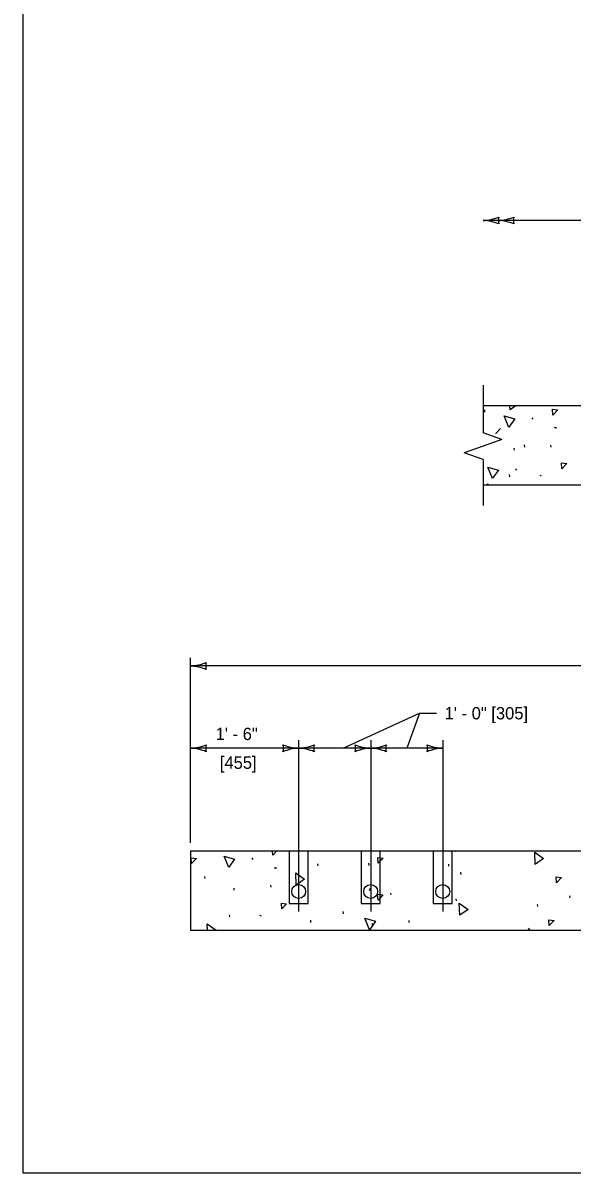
# Model space of a CAD drawing. Extents: x 49991.4 to 50021, y 49987.6 to 50011.4.
# Drawn here: x 49999.38 to 50002.06, y 49987.8 to 49993.39 of the extents above; entities that cross this region are included whole.
import ezdxf

# ---------------------------------------------------------------- set-up
doc = ezdxf.new("R2010")
doc.units = 0
for name, color, linetype in [('Level 1', 7, 'Continuous'), ('Level 2', 7, 'Continuous'), ('Level 3', 7, 'Continuous'), ('Level 4', 7, 'Continuous'), ('Level 5', 7, 'Continuous'), ('Level 6', 7, 'Continuous'), ('Level 9', 7, 'Continuous')]:
    doc.layers.add(name, color=color, linetype=linetype)

msp = doc.modelspace()

# ---------------------------------------------------------------- linework, layer by layer
at = {"layer": 'Level 1'}
for p, q in [((50001.6187, 49991.5298), (50007.3102, 49991.5298)), ((50001.6187, 49991.1448), (50003.1125, 49991.1448)), ((50008.5975, 49989.3638), (50000.1975, 49989.3638)), ((50000.1975, 49989.3638), (50000.1975, 49988.9788)), ((50000.1975, 49988.9788), (50008.5975, 49988.9788))]:
    msp.add_line(p, q, dxfattribs=at)
msp.add_lwpolyline([(49999.3835, 49998.9992), (50016.7501, 49998.9992), (50016.7501, 49987.7988), (49999.3835, 49987.7988)], close=True, dxfattribs=at)
at = {"layer": 'Level 3'}
for p, q in [((50003.1103, 49992.4298), (50001.6187, 49992.4298)), ((50000.1973, 49989.4039), (50000.1973, 49990.3039)), ((50004.3975, 49990.2638), (50000.1975, 49990.2638)), ((50001.31, 49990.0342), (50001.392, 49990.0342)), ((50000.7225, 49989.8638), (50000.1975, 49989.8638)), ((50001.0725, 49989.8638), (50000.7225, 49989.8638)), ((50001.4225, 49989.8638), (50001.0725, 49989.8638)), ((50001.0663, 49989.1728), (50001.0721, 49989.1859))]:
    msp.add_line(p, q, dxfattribs=at)
msp.add_lwpolyline([(50000.9387, 49989.8638), (50001.31, 49990.0342), (50001.2475, 49989.8638)], dxfattribs=at)
for centre in [(50000.7225, 49989.1676), (50001.0725, 49989.1676), (50001.4225, 49989.1676)]:
    msp.add_circle(centre, 0.0338, dxfattribs=at)
for centre, radius, start, end in [((50001.6096, 49992.6519), 0.2223, 272.3605, 292.544), ((50001.6072, 49992.1971), 0.233, 67.9228, 87.1727), ((50001.7469, 49992.4298), 0.0548, 162.1388, 197.8612), ((50001.683, 49992.6519), 0.2223, 272.3605, 292.544), ((50001.6807, 49992.1971), 0.233, 67.9228, 87.1727), ((50001.8204, 49992.4298), 0.0548, 162.1388, 197.8612), ((50000.1883, 49990.486), 0.2223, 272.3605, 292.544), ((50000.186, 49990.0311), 0.233, 67.9228, 87.1727), ((50000.3257, 49990.2638), 0.0548, 162.1388, 197.8612), ((50000.1883, 49990.086), 0.2223, 272.3605, 292.544), ((50000.186, 49989.6311), 0.233, 67.9228, 87.1727), ((50000.3257, 49989.8638), 0.0548, 162.1388, 197.8612), ((50000.5943, 49989.8638), 0.0548, 342.1388, 17.8612), ((50000.734, 49990.0966), 0.233, 247.9228, 267.1727), ((50000.7317, 49989.6417), 0.2223, 92.3605, 112.544), ((50000.7133, 49990.086), 0.2223, 272.3605, 292.544), ((50000.711, 49989.6311), 0.233, 67.9228, 87.1727), ((50000.8507, 49989.8638), 0.0548, 162.1388, 197.8612), ((50000.9443, 49989.8638), 0.0548, 342.1388, 17.8612), ((50001.084, 49990.0966), 0.233, 247.9228, 267.1727), ((50001.0817, 49989.6417), 0.2223, 92.3605, 112.544), ((50001.0633, 49990.086), 0.2223, 272.3605, 292.544), ((50001.061, 49989.6311), 0.233, 67.9228, 87.1727), ((50001.2007, 49989.8638), 0.0548, 162.1388, 197.8612), ((50001.2943, 49989.8638), 0.0548, 342.1388, 17.8612), ((50001.434, 49990.0966), 0.233, 247.9228, 267.1727), ((50001.4317, 49989.6417), 0.2223, 92.3605, 112.544)]:
    msp.add_arc(centre, radius, start, end, dxfattribs=at)
at = {"layer": 'Level 4'}
for p, q in [((50001.6276, 49991.4986), (50001.6265, 49991.5087)), ((50001.8556, 49991.4708), (50001.8611, 49991.4633)), ((50001.9639, 49991.4247), (50001.9706, 49991.4213)), ((50001.9687, 49991.4247), (50001.9754, 49991.4214)), ((50001.771, 49991.3133), (50001.7699, 49991.3234)), ((50001.8216, 49991.3283), (50001.8206, 49991.3384)), ((50001.9493, 49991.3276), (50001.9483, 49991.3377)), ((50001.7486, 49991.1842), (50001.7475, 49991.1943)), ((50001.7758, 49991.2227), (50001.7814, 49991.2152)), ((50001.8939, 49991.1915), (50001.9006, 49991.1882)), ((50000.4947, 49989.3309), (50000.5002, 49989.3234)), ((50000.8175, 49989.2924), (50000.8164, 49989.3026)), ((50001.0649, 49989.2944), (50001.0638, 49989.3045)), ((50001.453, 49989.2908), (50001.4519, 49989.301)), ((50000.2684, 49989.2303), (50000.2673, 49989.2405)), ((50000.603, 49989.2848), (50000.6097, 49989.2815)), ((50000.6078, 49989.2848), (50000.6145, 49989.2815)), ((50001.5116, 49989.2505), (50001.5106, 49989.2607)), ((50000.4101, 49989.1734), (50000.409, 49989.1835)), ((50000.5885, 49989.1877), (50000.5874, 49989.1978)), ((50001.1664, 49989.16), (50001.172, 49989.1524)), ((50001.4893, 49989.1214), (50001.4882, 49989.1316)), ((50002.0417, 49989.1365), (50002.0406, 49989.1466)), ((50000.9401, 49989.0593), (50000.939, 49989.0695)), ((50001.884, 49989.0946), (50001.883, 49989.1047)), ((50000.3877, 49989.0443), (50000.3867, 49989.0544)), ((50000.533, 49989.0516), (50000.5397, 49989.0483)), ((50000.7825, 49989.0174), (50000.7814, 49989.0275)), ((50001.0818, 49989.0024), (50001.0808, 49989.0126)), ((50001.2602, 49989.0167), (50001.2591, 49989.0269)), ((50001.8382, 49988.989), (50001.8438, 49988.9814))]:
    msp.add_line(p, q, dxfattribs=at)
for points in [[(50001.7495, 49991.5091), (50001.7488, 49991.5298)], [(50001.7793, 49991.5298), (50001.7504, 49991.5097)], [(50001.7438, 49991.424), (50001.7213, 49991.4793), (50001.7726, 49991.4647), (50001.7444, 49991.4248)], [(50001.9576, 49991.4832), (50001.9554, 49991.5119), (50001.9811, 49991.5088), (50001.9576, 49991.4832)], [(50001.7033, 49991.4191), (50001.7034, 49991.4191), (50001.6798, 49991.3936)], [(50001.6798, 49991.3936), (50001.6797, 49991.3955)], [(50002.0016, 49991.2226), (50001.9994, 49991.2512), (50002.0251, 49991.2481), (50002.0016, 49991.2226)], [(50001.664, 49991.1758), (50001.6415, 49991.2312), (50001.6928, 49991.2166), (50001.6646, 49991.1766)], [(50001.6395, 49991.1448), (50001.6393, 49991.1498), (50001.6462, 49991.1448)], [(50000.5967, 49989.3433), (50000.5951, 49989.3638)], [(50000.6156, 49989.3638), (50000.5967, 49989.3433)], [(50001.4844, 49989.3612), (50001.4833, 49989.3638)], [(50001.4864, 49989.3638), (50001.4851, 49989.362)], [(50001.8716, 49989.2993), (50001.8694, 49989.3591), (50001.9126, 49989.3278), (50001.8725, 49989.2998)], [(50000.2027, 49989.3031), (50000.2005, 49989.3317), (50000.2262, 49989.3286), (50000.2027, 49989.3031)], [(50000.3829, 49989.2841), (50000.3604, 49989.3394), (50000.4117, 49989.3248), (50000.3835, 49989.2849)], [(50001.1089, 49989.3044), (50001.1067, 49989.3331), (50001.1324, 49989.33), (50001.1089, 49989.3044)], [(50000.7104, 49989.1983), (50000.7082, 49989.258), (50000.7514, 49989.2267), (50000.7113, 49989.1988)], [(50001.976, 49989.2093), (50001.9738, 49989.2379), (50001.9995, 49989.2348), (50001.976, 49989.2093)], [(50001.1086, 49989.1257), (50001.1064, 49989.1544), (50001.1321, 49989.1513), (50001.1086, 49989.1257)], [(50000.6407, 49989.0827), (50000.6385, 49989.1113), (50000.6642, 49989.1082), (50000.6407, 49989.0827)], [(50001.5052, 49989.0516), (50001.503, 49989.1113), (50001.5462, 49989.08), (50001.5061, 49989.0521)], [(50000.2795, 49988.9788), (50000.2784, 49989.0099), (50000.3212, 49988.9788)], [(50001.0671, 49988.9816), (50001.0446, 49989.037), (50001.0959, 49989.0224), (50001.0678, 49988.9824)], [(50001.9402, 49989.0014), (50001.938, 49989.03), (50001.9638, 49989.0269), (50001.9402, 49989.0014)]]:
    msp.add_lwpolyline(points, dxfattribs=at)
at = {"layer": 'Level 5'}
for p, q in [((50000.7225, 49989.9038), (50000.7225, 49989.0708)), ((50001.0725, 49989.9038), (50001.0725, 49989.0708)), ((50001.4225, 49989.9038), (50001.4225, 49989.0708))]:
    msp.add_line(p, q, dxfattribs=at)
at = {"layer": 'Level 6'}
for p, q in [((50001.6187, 49991.6298), (50001.6187, 49991.3974)), ((50001.7101, 49991.365), (50001.6187, 49991.3974)), ((50001.7101, 49991.365), (50001.6187, 49991.3326)), ((50001.6187, 49991.3326), (50001.5273, 49991.3002)), ((50001.6187, 49991.2678), (50001.5273, 49991.3002)), ((50001.6187, 49991.2678), (50001.6187, 49991.0448))]:
    msp.add_line(p, q, dxfattribs=at)
at = {"layer": 'Level 9'}
for p, q in [((50000.6764, 49989.3575), (50000.6764, 49989.1897)), ((50000.7627, 49989.3633), (50000.6822, 49989.3633)), ((50000.7686, 49989.1897), (50000.7686, 49989.3575)), ((50001.0264, 49989.3575), (50001.0264, 49989.1897)), ((50001.1127, 49989.3633), (50001.0322, 49989.3633)), ((50001.1186, 49989.1897), (50001.1186, 49989.3575)), ((50001.3764, 49989.3575), (50001.3764, 49989.1897)), ((50001.4627, 49989.3633), (50001.3822, 49989.3633)), ((50001.4686, 49989.1897), (50001.4686, 49989.3575)), ((50000.6764, 49989.1897), (50000.6764, 49989.1093)), ((50000.7686, 49989.1093), (50000.7686, 49989.1897)), ((50001.0264, 49989.1897), (50001.0264, 49989.1093)), ((50001.1186, 49989.1093), (50001.1186, 49989.1897)), ((50001.3764, 49989.1897), (50001.3764, 49989.1093)), ((50001.4686, 49989.1093), (50001.4686, 49989.1897)), ((50000.6764, 49989.1093), (50000.7686, 49989.1093)), ((50001.0264, 49989.1093), (50001.1186, 49989.1093)), ((50001.3764, 49989.1093), (50001.4686, 49989.1093))]:
    msp.add_line(p, q, dxfattribs=at)
for centre, start, end in [((50000.6822, 49989.3575), 90, 180), ((50000.7627, 49989.3575), 0, 90), ((50001.0322, 49989.3575), 90, 180), ((50001.1127, 49989.3575), 0, 90), ((50001.3822, 49989.3575), 90, 180), ((50001.4627, 49989.3575), 0, 90)]:
    msp.add_arc(centre, 0.00583, start, end, dxfattribs=at)

# ---------------------------------------------------------------- texts
at = {"layer": 'Level 2'}
for s, p in [('1\' - 0" [305]', (50001.432, 49990.0042)), ('1\' - 6"', (50000.3195, 49989.9038)), ('[455]', (50000.3398, 49989.7638))]:
    msp.add_text(s, height=0.06, dxfattribs=at).set_placement(p)

doc.saveas('drawing.dxf')
